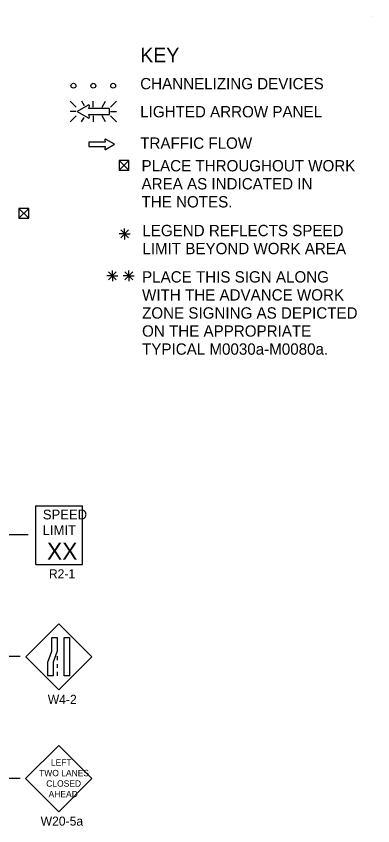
# Model space of a CAD drawing. Extents: x 16590 to 19508, y 5703 to 6974.
# Drawn here: x 18160 to 18453, y 6267 to 6931 of the extents above; entities that cross this region are included whole.
import ezdxf

# ---------------------------------------------------------------- set-up
doc = ezdxf.new("R2010")
doc.units = 0
for name, color, linetype in [('BORDER', 7, 'Continuous'), ('MT_SCRATCH_LEVEL_E', 7, 'Continuous'), ('TRAFFIC_SIGNS_PR', 7, 'Continuous'), ('TYPICAL_TEXT_DIMEN_EX', 7, 'Continuous'), ('TYPICAL_TEXT_DIMEN_PR', 7, 'Continuous')]:
    doc.layers.add(name, color=color, linetype=linetype)

msp = doc.modelspace()

# ---------------------------------------------------------------- linework, layer by layer
at = {"layer": 'BORDER'}
msp.add_line((18452.55, 6930.8), (18452.55, 6930.8), dxfattribs=at)
msp.add_line((18452.55, 6930.8), (18452.55, 6930.8), dxfattribs=at)
at = {"layer": 'MT_SCRATCH_LEVEL_E'}
for p, q in [((18232.77, 6827.55), (18219.52, 6827.55)), ((18219.52, 6827.55), (18219.52, 6823.81)), ((18232.46, 6829.33), (18232.77, 6827.55)), ((18240.38, 6825.7), (18233.14, 6829.81)), ((18219.52, 6823.81), (18232.77, 6823.81)), ((18232.77, 6823.81), (18232.46, 6822.03)), ((18233.14, 6821.55), (18240.38, 6825.7))]:
    msp.add_line(p, q, dxfattribs=at)
for centre, start, end in [((18232.92, 6829.4), 60.42484, 189.96381), ((18232.92, 6821.96), 170.03619, 299.77312)]:
    msp.add_arc(centre, 0.463, start, end, dxfattribs=at)
at = {"layer": 'TRAFFIC_SIGNS_PR'}
for p, q in [((18203.97, 6861.12), (18208.9, 6856.19)), ((18215.73, 6857.31), (18213.52, 6861.13)), ((18223.05, 6856.19), (18223.05, 6861.13)), ((18230.29, 6856.19), (18233.14, 6861.13)), ((18237.2, 6856.19), (18242.14, 6861.13)), ((18208.9, 6852.64), (18203.97, 6852.64)), ((18203.97, 6844.15), (18208.9, 6849.08)), ((18213.48, 6844.15), (18215.59, 6847.81)), ((18223.05, 6849.08), (18223.05, 6844.15)), ((18233.18, 6844.15), (18230.33, 6849.08)), ((18237.2, 6852.64), (18242.14, 6852.64)), ((18237.2, 6849.08), (18242.14, 6844.15)), ((18175.89, 6529.15), (18214.34, 6529.15)), ((18175.89, 6481.09), (18175.89, 6529.15)), ((18214.34, 6481.09), (18214.34, 6529.15)), ((18175.89, 6481.09), (18214.34, 6481.09)), ((18194.75, 6432.41), (18167.59, 6405.25)), ((18221.9, 6405.25), (18194.75, 6432.41)), ((18167.59, 6405.25), (18194.75, 6378.1)), ((18193.5, 6405.74), (18193.5, 6402.54)), ((18194.75, 6378.1), (18221.9, 6405.25)), ((18193.5, 6399.34), (18193.5, 6396.14)), ((18193.5, 6392.94), (18193.5, 6389.74)), ((18194.72, 6332.59), (18167.53, 6305.4)), ((18221.91, 6305.4), (18194.72, 6332.59)), ((18167.53, 6305.4), (18194.72, 6278.21)), ((18194.72, 6278.21), (18221.91, 6305.4))]:
    msp.add_line(p, q, dxfattribs=at)
for points in [[(18218.98, 6857.91), (18209.69, 6852.64), (18218.98, 6847.32)], [(18219.85, 6847.94), (18219.45, 6850.21), (18236.47, 6850.21), (18236.47, 6855.01), (18219.45, 6855.01), (18219.86, 6857.3)]]:
    msp.add_lwpolyline(points, dxfattribs=at)
for points in [[(18193.5, 6420.99), (18193.5, 6409.81), (18190.16, 6400.93), (18190.16, 6389.74), (18185.66, 6389.74), (18185.66, 6400.93), (18189.01, 6409.81), (18189.01, 6420.99)], [(18203.64, 6420.99), (18203.64, 6389.74), (18199.14, 6389.74), (18199.14, 6420.99)]]:
    msp.add_lwpolyline(points, close=True, dxfattribs=at)
for centre in [(18206.76, 6873.75), (18223.06, 6873.75), (18239.36, 6873.75)]:
    msp.add_circle(centre, 2, dxfattribs=at)
for centre, radius, start, end in [((18219.27, 6857.39), 0.598, 350.73078, 118.89165), ((18219.26, 6847.84), 0.597, 241.48329, 9.95933)]:
    msp.add_arc(centre, radius, start, end, dxfattribs=at)
at = {"layer": 'TYPICAL_TEXT_DIMEN_PR'}
for p, q in [((18244.24, 6812.5), (18252.24, 6804.5)), ((18244.24, 6804.5), (18252.24, 6812.5)), ((18162.02, 6773.18), (18170.02, 6765.18)), ((18162.02, 6765.18), (18170.02, 6773.18)), ((18245.61, 6755.42), (18251.99, 6749.05)), ((18251.99, 6755.42), (18245.61, 6749.05)), ((18248.8, 6752.24), (18248.8, 6756.69)), ((18248.8, 6752.24), (18244.27, 6752.24)), ((18248.8, 6752.24), (18251.99, 6752.24)), ((18248.8, 6752.24), (18253.28, 6752.24)), ((18248.8, 6752.24), (18248.8, 6747.74)), ((18238.7, 6717.84), (18238.7, 6722.29)), ((18252.2, 6717.84), (18252.2, 6722.29)), ((18238.7, 6717.84), (18234.17, 6717.84)), ((18235.51, 6721.02), (18241.89, 6714.65)), ((18241.89, 6721.02), (18235.51, 6714.65)), ((18238.7, 6717.84), (18241.89, 6717.84)), ((18238.7, 6717.84), (18243.18, 6717.84)), ((18238.7, 6717.84), (18238.7, 6713.34)), ((18252.2, 6717.84), (18247.67, 6717.84)), ((18249.02, 6721.02), (18255.39, 6714.65)), ((18255.39, 6721.02), (18249.02, 6714.65)), ((18252.2, 6717.84), (18255.39, 6717.84)), ((18252.2, 6717.84), (18256.68, 6717.84)), ((18252.2, 6717.84), (18252.2, 6713.34)), ((18169.63, 6505.41), (18079.39, 6505.41)), ((18162.9, 6405.41), (18079.39, 6405.41)), ((18162.9, 6305.41), (18078.14, 6305.41))]:
    msp.add_line(p, q, dxfattribs=at)
for points in [[(18244.24, 6812.5), (18244.24, 6804.5), (18252.24, 6804.5), (18252.24, 6812.5)], [(18162.02, 6773.18), (18162.02, 6765.18), (18170.02, 6765.18), (18170.02, 6773.18)]]:
    msp.add_lwpolyline(points, close=True, dxfattribs=at)
msp.add_open_spline([(18340.39, 6742.62), (18340.41, 6742.62), (18340.42, 6742.62), (18340.42, 6742.62)], degree=2, dxfattribs=at)

# ---------------------------------------------------------------- texts
at = {"layer": 'TRAFFIC_SIGNS_PR'}
for s, height, p in [('SPEED', 8.01, (18181.66, 6518)), ('LIMIT', 8.01, (18181.5, 6505.18)), ('XX', 14.048, (18185.01, 6484.85)), ('R2-1', 7.449, (18186.58, 6469.64)), ('W4-2', 7.44, (18185.7, 6366.66)), ('LEFT', 5.206, (18188.25, 6315.95)), ('TWO LANES', 5.206, (18178.56, 6307.34)), ('CLOSED', 5.206, (18184.42, 6298.72)), ('AHEAD', 5.206, (18186.37, 6290.11)), ('W20-5a', 7.449, (18179.84, 6266.76))]:
    msp.add_text(s, height=height, dxfattribs=at).set_placement(p)
at = {"layer": 'TYPICAL_TEXT_DIMEN_EX'}
for s, height, p in [('KEY', 12, (18261.6, 6892.86)), ('CHANNELIZING DEVICES', 9.3, (18261.6, 6870.81)), ('LIGHTED ARROW PANEL', 9.3, (18261.6, 6847.81)), ('TRAFFIC FLOW', 9.3, (18261.6, 6822.01)), ('PLACE THROUGHOUT WORK', 9.3, (18262.69, 6803.49)), ('AREA AS INDICATED IN', 9.3, (18262.69, 6788.69)), ('THE NOTES.', 9.3, (18262.69, 6773.89)), ('LEGEND REFLECTS SPEED', 9.3, (18263.35, 6750.34)), ('LIMIT BEYOND WORK AREA', 9.3, (18263.35, 6735.54)), ('PLACE THIS SIGN ALONG', 9.3, (18263.11, 6712.3)), ('WITH THE ADVANCE WORK', 9.3, (18263.11, 6697.5)), ('ZONE SIGNING AS DEPICTED', 9.3, (18263.11, 6682.7)), ('ON THE APPROPRIATE', 9.3, (18263.11, 6667.9)), ('TYPICAL M0030a-M0080a.', 9.3, (18263.11, 6653.1))]:
    msp.add_text(s, height=height, dxfattribs=at).set_placement(p)

doc.saveas('drawing.dxf')
